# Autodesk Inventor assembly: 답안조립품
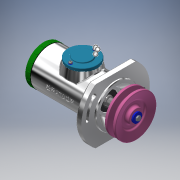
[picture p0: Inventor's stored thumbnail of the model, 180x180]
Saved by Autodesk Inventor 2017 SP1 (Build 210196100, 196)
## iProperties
Part Number: 답안조립품
Material: 일반
Document SubType Name: Assembly
Designer: MRC
Author: MRC
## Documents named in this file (22)
- C:\Users\MRC\Desktop\720506V1011\답안조립품.iam
- C:\Users\MRC\Desktop\720506V1011\본체.ipt
- C:\Users\MRC\Desktop\720506V1011\개스킷.ipt
- C:\Users\MRC\Desktop\720506V1011\사이드 커버.ipt
- 사이드 커버.ipt
- C:\Users\MRC\Desktop\720506V1011\축.ipt
- C:\Users\MRC\Desktop\720506V1011\멈춤링 15 x 1.ipt
- C:\Users\MRC\Desktop\720506V1011\멈춤링 35 x 1.6.ipt
- C:\Users\MRC\Desktop\720506V1011\베어링 6202.ipt
- C:\Users\MRC\Desktop\720506V1011\부시1.ipt
- C:\Users\MRC\Desktop\720506V1011\부시2.ipt
- C:\Users\MRC\Desktop\720506V1011\와셔 10 x 21.ipt
- C:\Users\MRC\Desktop\720506V1011\너트 M10.ipt
- C:\Users\MRC\Desktop\720506V1011\오일 실 15 x 30 x 7.ipt
- C:\Users\MRC\Desktop\720506V1011\키 4 x 4.ipt
- C:\Users\MRC\Desktop\720506V1011\V-벨트풀리.ipt
- C:\Users\MRC\Desktop\720506V1011\멈춤나사 M3.ipt
- C:\Users\MRC\Desktop\720506V1011\와셔 4 x 16.ipt
- C:\Users\MRC\Desktop\720506V1011\볼트 M4 x 10.ipt
- C:\Users\MRC\Desktop\720506V1011\탑 커버.ipt
- C:\Users\MRC\Desktop\720506V1011\와셔 3 x 6.ipt
- C:\Users\MRC\Desktop\720506V1011\십자볼트 M3 x 10.ipt
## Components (3 placed, 3 different names)
1. 개스킷:1
2. V-벨트풀리:1
3. ISO 4017 M4 x 10:1
